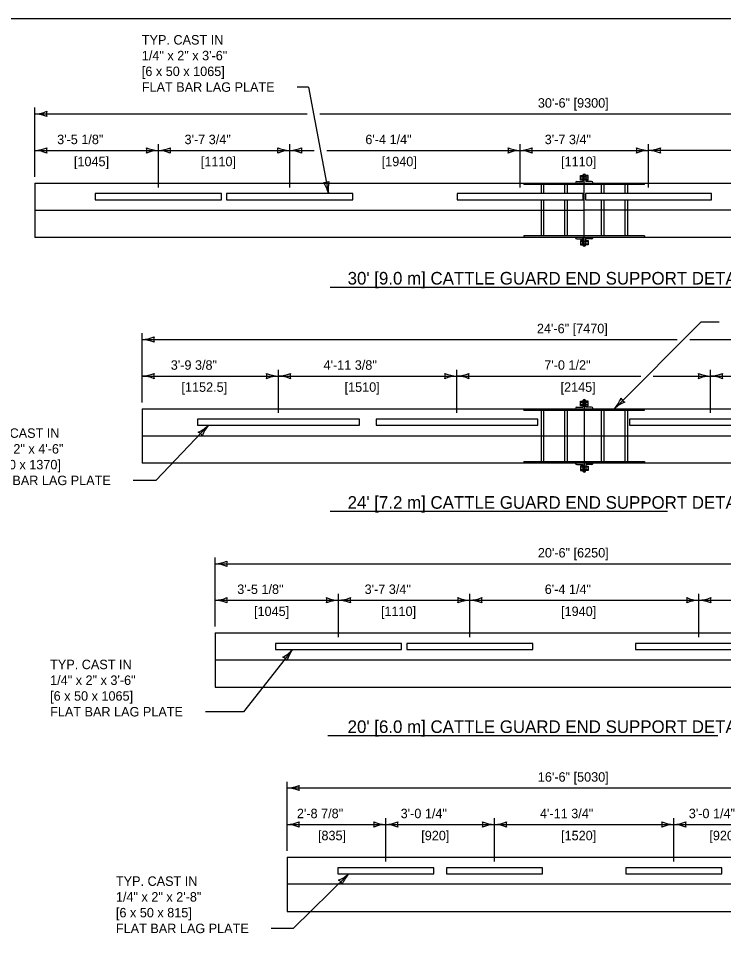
# Model space of a CAD drawing. Extents: x 49991.4 to 50021, y 49987.6 to 50011.4.
# Drawn here: x 50009.43 to 50013.9, y 49993.16 to 49999 of the extents above; entities that cross this region are included whole.
import ezdxf

# ---------------------------------------------------------------- set-up
doc = ezdxf.new("R2010")
doc.units = 0
for name, color, linetype in [('Level 1', 7, 'Continuous'), ('Level 2', 7, 'Continuous'), ('Level 3', 7, 'Continuous'), ('Level 4', 7, 'Continuous'), ('Level 5', 7, 'Continuous')]:
    doc.layers.add(name, color=color, linetype=linetype)

msp = doc.modelspace()

# ---------------------------------------------------------------- linework, layer by layer
at = {"layer": 'Level 1'}
for p, q in [((50012.9723, 49997.9643), (50013.0091, 49997.9643)), ((50012.9941, 49997.9733), (50012.9941, 49998.0018)), ((50012.9941, 49998.0018), (50013.0091, 49998.0018)), ((50012.9941, 49997.9946), (50013.0436, 49997.9946)), ((50012.9941, 49997.9804), (50013.0436, 49997.9804)), ((50013.0091, 49997.9733), (50012.9941, 49997.9733)), ((50013.0091, 49998.0018), (50013.0091, 49997.9643)), ((50013.0188, 49997.5532), (50013.0188, 49998.0108)), ((50013.0436, 49998.0018), (50013.0285, 49998.0018)), ((50013.0285, 49998.0018), (50013.0286, 49997.9643)), ((50013.0286, 49997.9733), (50013.0436, 49997.9733)), ((50013.0653, 49997.9643), (50013.0286, 49997.9643)), ((50013.0436, 49997.9733), (50013.0436, 49998.0018)), ((50009.5326, 49997.9545), (50016.5051, 49997.9545)), ((50009.5326, 49997.9545), (50009.5326, 49997.6095)), ((50012.6363, 49997.9545), (50012.6363, 49997.9448)), ((50013.4013, 49997.9448), (50012.6363, 49997.9448)), ((50012.7446, 49997.9448), (50012.7446, 49997.8874)), ((50012.7606, 49997.9448), (50012.7606, 49997.8874)), ((50012.8946, 49997.9448), (50012.8946, 49997.8874)), ((50012.9106, 49997.9448), (50012.9106, 49997.8874)), ((50013.1271, 49997.9448), (50013.1271, 49997.8874)), ((50013.1431, 49997.9448), (50013.1431, 49997.8874)), ((50013.2771, 49997.9448), (50013.2771, 49997.8874)), ((50013.2931, 49997.9448), (50013.2931, 49997.8874)), ((50013.4013, 49997.9448), (50013.4013, 49997.9545)), ((50010.716, 49997.8874), (50009.9159, 49997.8874)), ((50009.9159, 49997.8874), (50009.9159, 49997.8491)), ((50009.9159, 49997.8491), (50010.716, 49997.8491)), ((50010.716, 49997.8491), (50010.716, 49997.8874)), ((50011.5495, 49997.8874), (50010.7493, 49997.8874)), ((50010.7493, 49997.8874), (50010.7493, 49997.8491)), ((50010.7493, 49997.8491), (50011.5495, 49997.8491)), ((50011.5495, 49997.8491), (50011.5495, 49997.8874)), ((50013.0115, 49997.8874), (50012.2114, 49997.8874)), ((50012.2114, 49997.8874), (50012.2114, 49997.8491)), ((50012.2114, 49997.8491), (50013.0115, 49997.8491)), ((50012.7446, 49997.8491), (50012.7446, 49997.6192)), ((50012.7606, 49997.8491), (50012.7606, 49997.6192)), ((50012.8946, 49997.8491), (50012.8946, 49997.6192)), ((50012.9106, 49997.8491), (50012.9106, 49997.6192)), ((50013.0115, 49997.8491), (50013.0115, 49997.8874)), ((50013.8262, 49997.8874), (50013.0261, 49997.8874)), ((50013.0261, 49997.8874), (50013.0261, 49997.8491)), ((50013.0261, 49997.8491), (50013.8262, 49997.8491)), ((50013.1271, 49997.8491), (50013.1271, 49997.6192)), ((50013.1431, 49997.8491), (50013.1431, 49997.6192)), ((50013.2771, 49997.8491), (50013.2771, 49997.6192)), ((50013.2931, 49997.8491), (50013.2931, 49997.6192)), ((50013.8262, 49997.8491), (50013.8262, 49997.8874)), ((50009.5326, 49997.782), (50013.0188, 49997.782)), ((50016.5051, 49997.782), (50013.0188, 49997.782)), ((50016.5051, 49997.6095), (50009.5326, 49997.6095)), ((50013.4013, 49997.6192), (50012.6363, 49997.6192)), ((50012.6363, 49997.6192), (50012.6363, 49997.6095)), ((50013.0091, 49997.5622), (50013.0091, 49997.6095)), ((50013.0285, 49997.5622), (50013.0286, 49997.6095)), ((50013.4013, 49997.6192), (50013.4013, 49997.6095)), ((50012.9723, 49997.5997), (50013.0091, 49997.5997)), ((50013.0091, 49997.5907), (50012.9941, 49997.5907)), ((50012.9941, 49997.5907), (50012.9941, 49997.5622)), ((50012.9941, 49997.5836), (50013.0436, 49997.5836)), ((50012.9941, 49997.5694), (50013.0436, 49997.5694)), ((50012.9941, 49997.5622), (50013.0091, 49997.5622)), ((50013.0436, 49997.5622), (50013.0285, 49997.5622)), ((50013.0653, 49997.5997), (50013.0286, 49997.5997)), ((50013.0286, 49997.5907), (50013.0436, 49997.5907)), ((50013.0436, 49997.5907), (50013.0436, 49997.5622)), ((50010.2124, 49996.5232), (50010.2124, 49996.1782)), ((50010.2124, 49996.5232), (50015.8133, 49996.5232)), ((50011.5924, 49996.4561), (50010.5649, 49996.4561)), ((50010.5649, 49996.4561), (50010.5649, 49996.4178)), ((50011.5924, 49996.4178), (50011.5924, 49996.4561)), ((50012.7249, 49996.4561), (50011.6974, 49996.4561)), ((50011.6974, 49996.4561), (50011.6974, 49996.4178)), ((50012.7249, 49996.4178), (50012.7249, 49996.4561)), ((50014.3336, 49996.4561), (50013.3061, 49996.4561)), ((50013.3061, 49996.4561), (50013.3061, 49996.4178)), ((50010.5649, 49996.4178), (50011.5924, 49996.4178)), ((50011.6974, 49996.4178), (50012.7249, 49996.4178)), ((50013.3061, 49996.4178), (50014.3336, 49996.4178)), ((50010.2124, 49996.3507), (50015.8133, 49996.3507)), ((50015.8133, 49996.1782), (50010.2124, 49996.1782)), ((50010.6756, 49995.1007), (50010.6756, 49994.7557)), ((50010.6756, 49995.1007), (50015.3621, 49995.1007)), ((50011.859, 49995.0336), (50011.0589, 49995.0336)), ((50011.0589, 49995.0336), (50011.0589, 49994.9953)), ((50011.0589, 49994.9953), (50011.859, 49994.9953)), ((50011.859, 49994.9953), (50011.859, 49995.0336)), ((50012.6925, 49995.0336), (50011.8923, 49995.0336)), ((50011.8923, 49995.0336), (50011.8923, 49994.9953)), ((50011.8923, 49994.9953), (50012.6925, 49994.9953)), ((50012.6925, 49994.9953), (50012.6925, 49995.0336)), ((50014.1453, 49995.0336), (50013.3452, 49995.0336)), ((50013.3452, 49995.0336), (50013.3452, 49994.9953)), ((50013.3452, 49994.9953), (50014.1453, 49994.9953)), ((50015.3621, 49994.9282), (50010.6756, 49994.9282)), ((50010.6756, 49994.7557), (50015.3621, 49994.7557)), ((50011.1328, 49993.6782), (50011.1328, 49993.3332)), ((50011.1328, 49993.6782), (50014.9049, 49993.6782)), ((50012.0638, 49993.611), (50011.4542, 49993.611)), ((50011.4542, 49993.611), (50011.4542, 49993.5729)), ((50012.0638, 49993.5729), (50012.0638, 49993.611)), ((50012.7549, 49993.611), (50012.1453, 49993.611)), ((50012.1453, 49993.611), (50012.1453, 49993.5729)), ((50012.7549, 49993.5729), (50012.7549, 49993.611)), ((50013.8923, 49993.611), (50013.2827, 49993.611)), ((50013.2827, 49993.611), (50013.2827, 49993.5729)), ((50013.8923, 49993.5729), (50013.8923, 49993.611)), ((50011.4542, 49993.5729), (50012.0638, 49993.5729)), ((50012.1453, 49993.5729), (50012.7549, 49993.5729)), ((50013.2827, 49993.5729), (50013.8923, 49993.5729)), ((50014.9049, 49993.5057), (50011.1328, 49993.5057)), ((50011.1328, 49993.3332), (50014.9049, 49993.3332))]:
    msp.add_line(p, q, dxfattribs=at)
msp.add_lwpolyline([(49999.3835, 49998.9992), (50016.7501, 49998.9992), (50016.7501, 49987.7988), (49999.3835, 49987.7988)], close=True, dxfattribs=at)
for centre, start, end in [((50012.9723, 49997.9545), 90, 180), ((50013.0188, 49998.001), 4.41171, 175.58829), ((50013.0653, 49997.9545), 0, 90), ((50012.9723, 49997.6095), 180, 270), ((50013.0653, 49997.6095), 270, 0), ((50013.0188, 49997.563), 184.41174, 355.58827)]:
    msp.add_arc(centre, 0.00975, start, end, dxfattribs=at)
at = {"layer": 'Level 2'}
for p, q in [((50011.4064, 49997.2946), (50013.0779, 49997.2946)), ((50011.8387, 49997.2947), (50014.2011, 49997.2947)), ((50011.4064, 49995.8721), (50013.0779, 49995.8721)), ((50011.8161, 49995.8722), (50013.5465, 49995.8722)), ((50011.3913, 49994.4496), (50013.0628, 49994.4496)), ((50011.8141, 49994.4496), (50013.8671, 49994.4496))]:
    msp.add_line(p, q, dxfattribs=at)
at = {"layer": 'Level 3'}
for p, q in [((50011.2693, 49998.5634), (50011.1962, 49998.5634)), ((50011.2693, 49998.5634), (50011.3956, 49997.8874)), ((50009.5326, 49997.9945), (50009.5326, 49998.433)), ((50009.5326, 49998.393), (50011.2612, 49998.393)), ((50011.3412, 49998.393), (50016.5051, 49998.393)), ((50009.5326, 49998.1614), (50010.316, 49998.1614)), ((50010.316, 49998.1614), (50011.1494, 49998.1614)), ((50011.1494, 49998.1614), (50011.3044, 49998.1614)), ((50011.3844, 49998.1614), (50012.6115, 49998.1614)), ((50012.6115, 49998.1614), (50013.4262, 49998.1614)), ((50014.8882, 49998.1614), (50013.4262, 49998.1614)), ((50013.7615, 49997.0746), (50013.2101, 49996.5232)), ((50013.7615, 49997.0746), (50013.8754, 49997.0746)), ((50010.2124, 49996.5632), (50010.2124, 49997.0017)), ((50010.2124, 49996.9617), (50013.6085, 49996.9617)), ((50013.6885, 49996.9617), (50015.8133, 49996.9617)), ((50010.2124, 49996.7301), (50011.0786, 49996.7301)), ((50011.0786, 49996.7301), (50012.2111, 49996.7301)), ((50012.2111, 49996.7301), (50013.377, 49996.7301)), ((50013.457, 49996.7301), (50013.8199, 49996.7301)), ((50013.8199, 49996.7301), (50014.9524, 49996.7301)), ((50010.6344, 49996.4178), (50010.3007, 49996.0682)), ((50010.3007, 49996.0682), (50010.1563, 49996.0682)), ((50010.6756, 49995.1407), (50010.6756, 49995.5792)), ((50010.6756, 49995.5392), (50015.3621, 49995.5392)), ((50010.6756, 49995.3076), (50011.459, 49995.3076)), ((50011.459, 49995.3076), (50012.2924, 49995.3076)), ((50012.2924, 49995.3076), (50013.7452, 49995.3076)), ((50013.7452, 49995.3076), (50014.5787, 49995.3076)), ((50011.1672, 49994.9953), (50010.8559, 49994.6005)), ((50010.8559, 49994.6005), (50010.6143, 49994.6005)), ((50011.1328, 49993.7182), (50011.1328, 49994.1567)), ((50011.1328, 49994.1167), (50014.9049, 49994.1167)), ((50011.1328, 49993.8851), (50011.759, 49993.885)), ((50011.759, 49993.885), (50012.4501, 49993.885)), ((50012.4501, 49993.885), (50013.5875, 49993.885)), ((50013.5875, 49993.885), (50014.2786, 49993.885)), ((50011.5257, 49993.5729), (50011.172, 49993.2258)), ((50011.172, 49993.2258), (50011.0318, 49993.2258))]:
    msp.add_line(p, q, dxfattribs=at)
for centre, radius, start, end in [((50009.5211, 49998.6257), 0.233, 272.82731, 292.07716), ((50009.5234, 49998.1708), 0.2223, 67.45601, 87.63952), ((50009.6608, 49998.393), 0.0548, 162.13882, 197.86118), ((50009.5211, 49998.3941), 0.233, 272.82731, 292.07716), ((50009.5234, 49997.9393), 0.2223, 67.45601, 87.63952), ((50009.6608, 49998.1614), 0.0548, 162.13882, 197.86118), ((50010.3251, 49998.3835), 0.2223, 247.45601, 267.63952), ((50010.1878, 49998.1614), 0.0548, 342.13882, 17.86118), ((50010.3275, 49997.9287), 0.233, 92.82731, 112.07716), ((50010.3045, 49998.3941), 0.233, 272.82731, 292.07716), ((50010.3068, 49997.9393), 0.2223, 67.45601, 87.63952), ((50010.4442, 49998.1614), 0.0548, 162.13882, 197.86118), ((50011.1586, 49998.3835), 0.2223, 247.45601, 267.63952), ((50011.0212, 49998.1614), 0.0548, 342.13882, 17.86118), ((50011.1609, 49997.9287), 0.233, 92.82731, 112.07716), ((50011.1379, 49998.3941), 0.233, 272.82731, 292.07716), ((50011.1402, 49997.9393), 0.2223, 67.45601, 87.63952), ((50011.2776, 49998.1614), 0.0548, 162.13882, 197.86118), ((50012.6206, 49998.3835), 0.2223, 247.45601, 267.63952), ((50012.4833, 49998.1614), 0.0548, 342.13882, 17.86118), ((50012.623, 49997.9287), 0.233, 92.82731, 112.07716), ((50012.6, 49998.3941), 0.233, 272.82731, 292.07716), ((50012.6023, 49997.9393), 0.2223, 67.45601, 87.63952), ((50012.7397, 49998.1614), 0.0548, 162.13882, 197.86118), ((50013.4353, 49998.3835), 0.2223, 247.45601, 267.63952), ((50013.2979, 49998.1614), 0.0548, 342.13882, 17.86118), ((50013.4376, 49997.9287), 0.233, 92.82731, 112.07716), ((50013.4147, 49998.3941), 0.233, 272.82731, 292.07716), ((50013.417, 49997.9393), 0.2223, 67.45601, 87.63952), ((50013.5544, 49998.1614), 0.0548, 162.13882, 197.86118), ((50011.3721, 49998.0134), 0.0548, 262.72124, 298.4436), ((50011.169, 49997.8333), 0.233, 13.40973, 32.65958), ((50011.6157, 49997.9192), 0.2223, 168.03843, 188.22194), ((50010.2009, 49997.1944), 0.233, 272.82731, 292.07716), ((50010.3406, 49996.9617), 0.0548, 162.13882, 197.86118), ((50010.2032, 49996.7395), 0.2223, 67.45601, 87.63952), ((50010.2009, 49996.9628), 0.233, 272.82731, 292.07716), ((50010.2032, 49996.508), 0.2223, 67.45601, 87.63952), ((50010.3406, 49996.7301), 0.0548, 162.13882, 197.86118), ((50011.0878, 49996.9522), 0.2223, 247.45601, 267.63952), ((50010.9504, 49996.7301), 0.0548, 342.13882, 17.86118), ((50011.0901, 49996.4974), 0.233, 92.82731, 112.07716), ((50011.0671, 49996.9628), 0.233, 272.82731, 292.07716), ((50011.0695, 49996.508), 0.2223, 67.45601, 87.63952), ((50011.2069, 49996.7301), 0.0548, 162.13882, 197.86118), ((50012.2203, 49996.9522), 0.2223, 247.45601, 267.63952), ((50012.0829, 49996.7301), 0.0548, 342.13882, 17.86118), ((50012.2226, 49996.4974), 0.233, 92.82731, 112.07716), ((50012.1996, 49996.9628), 0.233, 272.82731, 292.07716), ((50012.202, 49996.508), 0.2223, 67.45601, 87.63952), ((50012.3394, 49996.7301), 0.0548, 162.13882, 197.86118), ((50013.829, 49996.9522), 0.2223, 247.45601, 267.63952), ((50013.6917, 49996.7301), 0.0548, 342.13882, 17.86118), ((50013.8314, 49996.4974), 0.233, 92.82731, 112.07716), ((50013.8084, 49996.9628), 0.233, 272.82731, 292.07716), ((50013.8107, 49996.508), 0.2223, 67.45601, 87.63952), ((50013.9481, 49996.7301), 0.0548, 162.13882, 197.86118), ((50013.0374, 49996.6796), 0.233, 317.82731, 337.07716), ((50013.3607, 49996.3597), 0.2223, 112.45601, 132.63952), ((50013.3007, 49996.6139), 0.0548, 207.13882, 242.86118), ((50010.48, 49996.5778), 0.2223, 293.79268, 313.97619), ((50010.8107, 49996.2655), 0.233, 139.16398, 158.41383), ((50010.5459, 49996.3251), 0.0548, 28.47549, 64.19785), ((50010.6641, 49995.7719), 0.233, 272.82731, 292.07716), ((50010.6664, 49995.317), 0.2223, 67.45601, 87.63952), ((50010.8038, 49995.5392), 0.0548, 162.13882, 197.86118), ((50010.6641, 49995.5403), 0.233, 272.82716, 292.07701), ((50010.6664, 49995.0855), 0.2223, 67.45586, 87.63936), ((50010.8038, 49995.3076), 0.0548, 162.13866, 197.86103), ((50011.4681, 49995.5297), 0.2223, 247.45586, 267.63936), ((50011.3308, 49995.3076), 0.0548, 342.13866, 17.86103), ((50011.4705, 49995.0749), 0.233, 92.82716, 112.07701), ((50011.4475, 49995.5403), 0.233, 272.82731, 292.07716), ((50011.4498, 49995.0855), 0.2223, 67.45601, 87.63952), ((50011.5872, 49995.3076), 0.0548, 162.13882, 197.86118), ((50012.3016, 49995.5297), 0.2223, 247.45601, 267.63952), ((50012.1642, 49995.3076), 0.0548, 342.13882, 17.86118), ((50012.3039, 49995.0749), 0.233, 92.82731, 112.07716), ((50012.2809, 49995.5403), 0.233, 272.82731, 292.07716), ((50012.2832, 49995.0855), 0.2223, 67.45601, 87.63952), ((50012.4206, 49995.3076), 0.0548, 162.13882, 197.86118), ((50013.7544, 49995.5297), 0.2223, 247.45601, 267.63952), ((50013.617, 49995.3076), 0.0548, 342.13882, 17.86118), ((50013.7567, 49995.0749), 0.233, 92.82731, 112.07716), ((50013.7337, 49995.5403), 0.233, 272.82731, 292.07716), ((50013.7361, 49995.0855), 0.2223, 67.45601, 87.63952), ((50013.8735, 49995.3076), 0.0548, 162.13882, 197.86118), ((50010.9985, 49995.14), 0.2223, 299.20341, 319.38692), ((50011.3571, 49994.8603), 0.233, 144.57471, 163.82456), ((50011.0879, 49994.8946), 0.0548, 33.88622, 69.60858), ((50011.1213, 49994.3494), 0.233, 272.82731, 292.07716), ((50011.1236, 49993.8945), 0.2223, 67.45601, 87.63952), ((50011.261, 49994.1167), 0.0548, 162.13882, 197.86118), ((50011.1213, 49994.1178), 0.233, 272.82041, 292.07026), ((50011.1236, 49993.663), 0.2223, 67.44911, 87.63261), ((50011.261, 49993.8851), 0.0548, 162.13191, 197.85428), ((50011.7682, 49994.1072), 0.2223, 247.44911, 267.63261), ((50011.6308, 49993.885), 0.0548, 342.13191, 17.85428), ((50011.7705, 49993.6523), 0.233, 92.82041, 112.07026), ((50011.7475, 49994.1177), 0.233, 272.82731, 292.07716), ((50011.7499, 49993.6629), 0.2223, 67.45601, 87.63952), ((50011.8872, 49993.885), 0.0548, 162.13882, 197.86118), ((50012.4593, 49994.1072), 0.2223, 247.45601, 267.63952), ((50012.3219, 49993.885), 0.0548, 342.13882, 17.86118), ((50012.4616, 49993.6523), 0.233, 92.82731, 112.07716), ((50012.4386, 49994.1177), 0.233, 272.82731, 292.07716), ((50012.441, 49993.6629), 0.2223, 67.45601, 87.63952), ((50012.5783, 49993.885), 0.0548, 162.13882, 197.86118), ((50013.5967, 49994.1072), 0.2223, 247.45601, 267.63952), ((50013.4593, 49993.885), 0.0548, 342.13882, 17.86118), ((50013.599, 49993.6523), 0.233, 92.82731, 112.07716), ((50013.576, 49994.1177), 0.233, 272.82731, 292.07716), ((50013.5784, 49993.6629), 0.2223, 67.45601, 87.63952), ((50013.7157, 49993.885), 0.0548, 162.13882, 197.86118), ((50011.3766, 49993.7379), 0.2223, 291.91743, 312.10094), ((50011.4342, 49993.4831), 0.0548, 26.60024, 62.3226), ((50011.6969, 49993.4149), 0.233, 137.28873, 156.53858)]:
    msp.add_arc(centre, radius, start, end, dxfattribs=at)
at = {"layer": 'Level 4'}
for p, q in [((50013.0091, 49997.9969), (50013.0285, 49997.9969)), ((50013.0091, 49997.9781), (50013.0286, 49997.9781)), ((50013.0091, 49997.5859), (50013.0286, 49997.5859)), ((50013.0091, 49997.5671), (50013.0285, 49997.5671)), ((50012.9941, 49996.542), (50012.9941, 49996.5705)), ((50012.9941, 49996.5705), (50013.0091, 49996.5705)), ((50013.0436, 49996.5633), (50012.9941, 49996.5633)), ((50013.0091, 49996.5705), (50013.0091, 49996.533)), ((50013.0286, 49996.5656), (50013.0091, 49996.5656)), ((50013.0188, 49996.5806), (50013.0188, 49996.1211)), ((50013.0436, 49996.5705), (50013.0286, 49996.5705)), ((50013.0286, 49996.533), (50013.0286, 49996.5705)), ((50013.0436, 49996.542), (50013.0436, 49996.5705)), ((50012.6363, 49996.5135), (50012.6363, 49996.5232)), ((50012.6363, 49996.5135), (50013.4013, 49996.5135)), ((50012.7446, 49996.5135), (50012.7446, 49996.1879)), ((50012.7606, 49996.5135), (50012.7606, 49996.1879)), ((50012.8946, 49996.5135), (50012.8946, 49996.1879)), ((50012.9106, 49996.5135), (50012.9106, 49996.1879)), ((50012.9723, 49996.533), (50013.0091, 49996.533)), ((50013.0436, 49996.5491), (50012.9941, 49996.5491)), ((50013.0091, 49996.542), (50012.9941, 49996.542)), ((50013.0286, 49996.5468), (50013.0091, 49996.5468)), ((50013.0286, 49996.542), (50013.0436, 49996.542)), ((50013.0653, 49996.533), (50013.0286, 49996.533)), ((50013.1271, 49996.5135), (50013.1271, 49996.1879)), ((50013.1431, 49996.5135), (50013.1431, 49996.1879)), ((50013.2771, 49996.5135), (50013.2771, 49996.1879)), ((50013.2931, 49996.5135), (50013.2931, 49996.1879)), ((50013.4013, 49996.5135), (50013.4013, 49996.5232)), ((50012.6363, 49996.1879), (50013.4013, 49996.1879)), ((50012.6363, 49996.1879), (50012.6363, 49996.1782)), ((50012.9723, 49996.1684), (50013.0091, 49996.1684)), ((50013.0091, 49996.1594), (50012.9941, 49996.1594)), ((50012.9941, 49996.1594), (50012.9941, 49996.1309)), ((50013.0436, 49996.1523), (50012.9941, 49996.1523)), ((50013.0091, 49996.1684), (50013.0091, 49996.1309)), ((50013.0286, 49996.1546), (50013.0091, 49996.1546)), ((50013.0653, 49996.1684), (50013.0286, 49996.1684)), ((50013.0286, 49996.1684), (50013.0286, 49996.1309)), ((50013.0286, 49996.1594), (50013.0436, 49996.1594)), ((50013.0436, 49996.1594), (50013.0436, 49996.1309)), ((50013.4013, 49996.1879), (50013.4013, 49996.1782)), ((50013.0436, 49996.1381), (50012.9941, 49996.1381)), ((50012.9941, 49996.1309), (50013.0091, 49996.1309)), ((50013.0286, 49996.1358), (50013.0091, 49996.1358)), ((50013.0436, 49996.1309), (50013.0286, 49996.1309))]:
    msp.add_line(p, q, dxfattribs=at)
for centre, radius, start, end in [((50013.0188, 49996.5709), 0.00976, 357.66539, 182.33461), ((50012.9723, 49996.5232), 0.00975, 90, 180), ((50013.0653, 49996.5232), 0.00975, 0, 90), ((50012.9723, 49996.1782), 0.00975, 180, 270), ((50013.0653, 49996.1782), 0.00975, 270, 0), ((50013.0188, 49996.1309), 0.00975, 179.68722, 0.31278)]:
    msp.add_arc(centre, radius, start, end, dxfattribs=at)
at = {"layer": 'Level 5'}
for p, q in [((50010.316, 49997.9274), (50010.316, 49998.2014)), ((50011.1494, 49997.9274), (50011.1494, 49998.2014)), ((50012.6115, 49997.9274), (50012.6115, 49998.2014)), ((50013.4262, 49997.9274), (50013.4262, 49998.2014)), ((50011.0786, 49996.4961), (50011.0786, 49996.7701)), ((50012.2111, 49996.4961), (50012.2111, 49996.7701)), ((50013.8199, 49996.4961), (50013.8199, 49996.7701)), ((50011.459, 49995.0736), (50011.459, 49995.3476)), ((50012.2924, 49995.0736), (50012.2924, 49995.3476)), ((50013.7452, 49995.0736), (50013.7452, 49995.3476)), ((50011.759, 49993.651), (50011.759, 49993.925)), ((50012.4501, 49993.651), (50012.4501, 49993.925)), ((50013.5875, 49993.651), (50013.5875, 49993.925))]:
    msp.add_line(p, q, dxfattribs=at)

# ---------------------------------------------------------------- texts
at = {"layer": 'Level 2'}
for s, height, p in [('TYP. CAST IN', 0.06, (50010.2112, 49998.8334)), ('1/4" x 2" x 3\'-6"', 0.06, (50010.2112, 49998.7334)), ('[6 x 50 x 1065]', 0.06, (50010.2112, 49998.6334)), ('FLAT BAR LAG PLATE', 0.06, (50010.2112, 49998.5334)), ('30\'-6" [9300]', 0.06, (50012.7245, 49998.433)), ('3\'-5 1/8"', 0.06, (50009.6737, 49998.2014)), ('3\'-7 3/4"', 0.06, (50010.4821, 49998.2014)), ('6\'-4 1/4"', 0.06, (50011.6298, 49998.2014)), ('3\'-7 3/4"', 0.06, (50012.7682, 49998.2014)), ('[1045]', 0.06, (50009.7802, 49998.0614)), ('[1110]', 0.06, (50010.5857, 49998.0614)), ('[1940]', 0.06, (50011.7334, 49998.0614)), ('[1110]', 0.06, (50012.8718, 49998.0614)), ("30' [9.0 m] CATTLE GUARD END SUPPORT DETAIL", 0.08, (50011.5172, 49997.3107)), ('24\'-6" [7470]', 0.06, (50012.7186, 49997.0017)), ('3\'-9 3/8"', 0.06, (50010.3949, 49996.7701)), ('4\'-11 3/8"', 0.06, (50011.3643, 49996.7701)), ('7\'-0 1/2"', 0.06, (50012.7651, 49996.7701)), ('[1152.5]', 0.06, (50010.4627, 49996.6301)), ('[1510]', 0.06, (50011.4979, 49996.6301)), ('[2145]', 0.06, (50012.8685, 49996.6301)), ('TYP. CAST IN', 0.06, (50009.1713, 49996.3382)), ('1/4" x 2" x 4\'-6"', 0.06, (50009.1713, 49996.2382)), ('[6 x 50 x 1370]', 0.06, (50009.1713, 49996.1382)), ('FLAT BAR LAG PLATE', 0.06, (50009.1713, 49996.0382)), ("24' [7.2 m] CATTLE GUARD END SUPPORT DETAIL", 0.08, (50011.5172, 49995.8882)), ('20\'-6" [6250]', 0.06, (50012.7245, 49995.5792)), ('3\'-5 1/8"', 0.06, (50010.8167, 49995.3476)), ('3\'-7 3/4"', 0.06, (50011.6251, 49995.3476)), ('6\'-4 1/4"', 0.06, (50012.7682, 49995.3476)), ('[1045]', 0.06, (50010.9232, 49995.2076)), ('[1110]', 0.06, (50011.7287, 49995.2076)), ('[1940]', 0.06, (50012.8718, 49995.2076)), ('TYP. CAST IN', 0.06, (50009.6293, 49994.8705)), ('1/4" x 2" x 3\'-6"', 0.06, (50009.6293, 49994.7705)), ('[6 x 50 x 1065]', 0.06, (50009.6293, 49994.6705)), ('FLAT BAR LAG PLATE', 0.06, (50009.6293, 49994.5705)), ("20' [6.0 m] CATTLE GUARD END SUPPORT DETAIL", 0.08, (50011.5172, 49994.4657)), ('16\'-6" [5030]', 0.06, (50012.7245, 49994.1567)), ('2\'-8 7/8"', 0.06, (50011.1953, 49993.9251)), ('3\'-0 1/4"', 0.06, (50011.8539, 49993.925)), ('4\'-11 3/4"', 0.06, (50012.7382, 49993.925)), ('3\'-0 1/4"', 0.06, (50013.6824, 49993.925)), ('[835]', 0.06, (50011.3288, 49993.7851)), ('[920]', 0.06, (50011.9845, 49993.785)), ('[1520]', 0.06, (50012.8718, 49993.785)), ('[920]', 0.06, (50013.813, 49993.785)), ('TYP. CAST IN', 0.06, (50010.0468, 49993.4958)), ('1/4" x 2" x 2\'-8"', 0.06, (50010.0468, 49993.3958)), ('[6 x 50 x 815]', 0.06, (50010.0468, 49993.2958)), ('FLAT BAR LAG PLATE', 0.06, (50010.0468, 49993.1958))]:
    msp.add_text(s, height=height, dxfattribs=at).set_placement(p)

doc.saveas('drawing.dxf')
